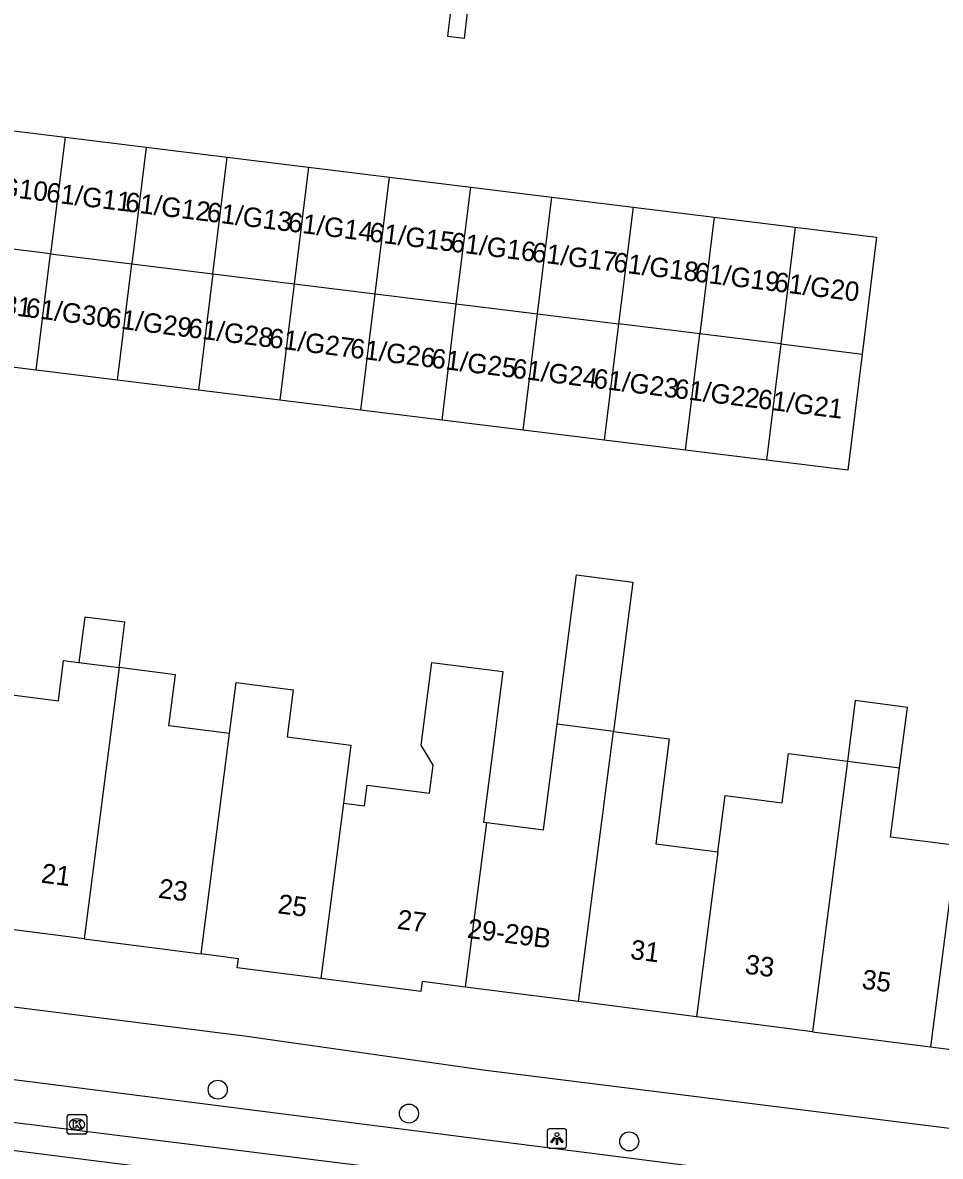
# Model space of a CAD drawing. Extents: x 161696 to 162377, y 380761 to 381673.
# Drawn here: x 161893.4 to 161940.5, y 381316.7 to 381375.1 of the extents above; entities that cross this region are included whole.
import ezdxf

# ---------------------------------------------------------------- set-up
doc = ezdxf.new("R2010")
doc.units = 0
for name, color, linetype in [('IMGEO_Boom', 7, 'Continuous'), ('IMGEO_Kolk', 7, 'Continuous'), ('IMGEO_Lichtpunt', 7, 'Continuous'), ('IMGEO_Pand', 7, 'Continuous'), ('IMGEO_Pand_nummerreeks', 7, 'Continuous'), ('IMGEO_Rijbaan_lokaal_gesloten', 7, 'Continuous'), ('IMGEO_Voetpad_open', 7, 'Continuous')]:
    doc.layers.add(name, color=color, linetype=linetype)

msp = doc.modelspace()

# ---------------------------------------------------------------- linework, layer by layer
at = {"layer": 'IMGEO_Boom'}
for centre in [(161903.383, 381320.171), (161913.22, 381318.941), (161924.549, 381317.51)]:
    msp.add_circle(centre, 0.489, dxfattribs=at)
at = {"layer": 'IMGEO_Kolk'}
for p, q in [((161895.646, 381317.96), (161895.646, 381318.812)), ((161895.721, 381318.886), (161896.573, 381318.886)), ((161896.647, 381318.812), (161896.647, 381317.96)), ((161896.134, 381318.666), (161896.159, 381318.666)), ((161896.573, 381317.886), (161895.721, 381317.886)), ((161896.157, 381318.106), (161896.132, 381318.106))]:
    msp.add_line(p, q, dxfattribs=at)
for points in [[(161895.646, 381317.96), (161895.646, 381318.812)], [(161895.721, 381318.886), (161896.573, 381318.886)], [(161896.647, 381318.812), (161896.647, 381317.96)], [(161895.967, 381318.586), (161896.09, 381318.586), (161896.09, 381318.435), (161896.22, 381318.586), (161896.384, 381318.586), (161896.238, 381318.435), (161896.391, 381318.186), (161896.239, 381318.186), (161896.154, 381318.35), (161896.09, 381318.283), (161896.09, 381318.186), (161895.967, 381318.186), (161895.967, 381318.586)], [(161896.573, 381317.886), (161895.721, 381317.886)]]:
    msp.add_lwpolyline(points, dxfattribs=at)
for centre, start, end in [((161895.723, 381318.81), 91.55205, 178.44795), ((161895.723, 381318.81), 91.55205, 178.44795), ((161896.571, 381318.81), 1.55205, 88.44795), ((161896.571, 381318.81), 1.55205, 88.44795), ((161895.723, 381317.962), 181.55205, 268.44795), ((161895.723, 381317.962), 181.55205, 268.44795), ((161896.571, 381317.962), 271.55205, 358.44795), ((161896.571, 381317.962), 271.55205, 358.44795)]:
    msp.add_arc(centre, 0.0765, start, end, dxfattribs=at)
for centre, major_axis, ratio, start_param, end_param in [((161896.133, 381318.386), (-0.387, 0.002), 0.722429, 4.712389, 7.853982), ((161896.158, 381318.386), (-0.39, 0.002), 0.717154, 1.570796, 4.712389)]:
    msp.add_ellipse(centre, major_axis=major_axis, ratio=ratio, start_param=start_param, end_param=end_param, dxfattribs=at)
at = {"layer": 'IMGEO_Lichtpunt'}
for p, q in [((161921.234, 381318.158), (161920.426, 381318.158)), ((161921.234, 381318.158), (161920.426, 381318.158)), ((161920.332, 381318.063), (161920.332, 381317.256)), ((161920.332, 381318.063), (161920.332, 381317.256)), ((161921.328, 381317.256), (161921.328, 381318.063)), ((161921.328, 381317.256), (161921.328, 381318.063)), ((161920.426, 381317.162), (161921.234, 381317.162)), ((161920.426, 381317.162), (161921.234, 381317.162))]:
    msp.add_line(p, q, dxfattribs=at)
for points in [[(161920.706, 381317.727), (161920.745, 381317.699), (161920.557, 381317.437), (161920.519, 381317.464), (161920.706, 381317.727)], [(161920.808, 381317.679), (161920.855, 381317.679), (161920.855, 381317.357), (161920.808, 381317.357), (161920.808, 381317.679)], [(161920.918, 381317.699), (161920.956, 381317.726), (161921.143, 381317.464), (161921.104, 381317.436), (161920.918, 381317.699)]]:
    msp.add_lwpolyline(points, dxfattribs=at)
msp.add_circle((161920.831, 381317.861), 0.0994, dxfattribs=at)
for centre, start, end in [((161920.426, 381318.063), 90, 180), ((161920.426, 381318.063), 90, 180), ((161921.234, 381318.063), 0, 90), ((161921.234, 381318.063), 0, 90), ((161920.426, 381317.256), 180, 270), ((161920.426, 381317.256), 180, 270), ((161921.234, 381317.256), 270, 0), ((161921.234, 381317.256), 270, 360)]:
    msp.add_arc(centre, 0.0946, start, end, dxfattribs=at)
at = {"layer": 'IMGEO_Pand'}
for points in [[(161915.217, 381374.347), (161915.253, 381374.661), (161915.3, 381375.07), (161915.573, 381377.467), (161915.598, 381377.683), (161916.454, 381377.582), (161916.429, 381377.366), (161916.358, 381376.764), (161916.097, 381374.561), (161916.06, 381374.247), (161915.217, 381374.347)], [(161891.357, 381369.683), (161895.53, 381369.17)], [(161895.53, 381369.17), (161894.791, 381363.166)], [(161895.53, 381369.17), (161899.704, 381368.656)], [(161899.704, 381368.656), (161898.964, 381362.652)], [(161899.704, 381368.656), (161903.877, 381368.142)], [(161903.137, 381362.137), (161903.877, 381368.142)], [(161903.877, 381368.142), (161908.05, 381367.628)], [(161908.05, 381367.628), (161907.31, 381361.622)], [(161908.05, 381367.628), (161912.223, 381367.114)], [(161911.483, 381361.107), (161912.223, 381367.114)], [(161912.223, 381367.114), (161916.396, 381366.6)], [(161915.656, 381360.592), (161916.396, 381366.6)], [(161916.396, 381366.6), (161920.569, 381366.086)], [(161919.829, 381360.078), (161920.569, 381366.086)], [(161920.569, 381366.086), (161924.743, 381365.572)], [(161924.743, 381365.572), (161924.002, 381359.563)], [(161924.743, 381365.572), (161928.916, 381365.058)], [(161928.916, 381365.058), (161928.176, 381359.048)], [(161928.916, 381365.058), (161933.089, 381364.544)], [(161933.089, 381364.544), (161932.349, 381358.533)], [(161933.089, 381364.544), (161937.262, 381364.03), (161936.522, 381358.018)], [(161894.791, 381363.166), (161890.618, 381363.681)], [(161894.054, 381357.181), (161894.791, 381363.166)], [(161894.791, 381363.166), (161898.964, 381362.652)], [(161898.227, 381356.667), (161898.964, 381362.652)], [(161898.964, 381362.652), (161903.137, 381362.137)], [(161903.137, 381362.137), (161902.4, 381356.153)], [(161903.137, 381362.137), (161907.31, 381361.622)], [(161907.31, 381361.622), (161906.573, 381355.639)], [(161907.31, 381361.622), (161911.483, 381361.107)], [(161910.747, 381355.125), (161911.483, 381361.107)], [(161911.483, 381361.107), (161915.656, 381360.592)], [(161914.92, 381354.611), (161915.656, 381360.592)], [(161915.656, 381360.592), (161919.829, 381360.078)], [(161919.093, 381354.098), (161919.829, 381360.078)], [(161919.829, 381360.078), (161924.002, 381359.563)], [(161924.002, 381359.563), (161923.266, 381353.584)], [(161928.176, 381359.048), (161924.002, 381359.563)], [(161927.439, 381353.07), (161928.176, 381359.048)], [(161932.349, 381358.533), (161928.176, 381359.048)], [(161932.349, 381358.533), (161931.612, 381352.556)], [(161932.349, 381358.533), (161936.522, 381358.018)], [(161936.522, 381358.018), (161935.786, 381352.042), (161931.612, 381352.556)], [(161894.054, 381357.181), (161889.881, 381357.695)], [(161898.227, 381356.667), (161894.054, 381357.181)], [(161902.4, 381356.153), (161898.227, 381356.667)], [(161906.573, 381355.639), (161902.4, 381356.153)], [(161910.747, 381355.125), (161906.573, 381355.639)], [(161914.92, 381354.611), (161910.747, 381355.125)], [(161919.093, 381354.098), (161914.92, 381354.611)], [(161923.266, 381353.584), (161919.093, 381354.098)], [(161927.439, 381353.07), (161923.266, 381353.584)], [(161931.612, 381352.556), (161927.439, 381353.07)], [(161920.843, 381338.97), (161921.532, 381344.314), (161921.834, 381346.661), (161924.73, 381346.288), (161923.875, 381339.654), (161923.739, 381338.597)], [(161898.309, 381341.882), (161898.61, 381344.22), (161896.547, 381344.487), (161896.245, 381342.148)], [(161891.941, 381339.132), (161892.127, 381340.577), (161895.191, 381340.182), (161895.457, 381342.25), (161896.245, 381342.148)], [(161896.245, 381342.148), (161898.309, 381341.882)], [(161909.848, 381334.907), (161910.935, 381334.767), (161911.073, 381335.837), (161914.282, 381335.424), (161914.468, 381336.864), (161913.846, 381337.902), (161914.394, 381342.152), (161918.053, 381341.681), (161917.759, 381339.402), (161917.636, 381338.447), (161917.055, 381333.937), (161917.226, 381333.915)], [(161898.309, 381341.882), (161896.511, 381327.93)], [(161903.99, 381338.488), (161900.876, 381338.889), (161901.214, 381341.508), (161898.309, 381341.882)], [(161903.99, 381338.488), (161904.328, 381341.112), (161907.259, 381340.735), (161906.947, 381338.315), (161910.233, 381337.891), (161909.848, 381334.907)], [(161938.453, 381336.733), (161938.853, 381339.84), (161936.175, 381340.185), (161935.775, 381337.078)], [(161917.226, 381333.915), (161920.143, 381333.539), (161920.843, 381338.97)], [(161923.739, 381338.597), (161920.843, 381338.97)], [(161921.948, 381324.702), (161923.739, 381338.597)], [(161923.739, 381338.597), (161926.61, 381338.227), (161925.912, 381332.812), (161929.106, 381332.4)], [(161902.529, 381327.155), (161903.629, 381335.69), (161903.99, 381338.488)], [(161929.106, 381332.4), (161929.481, 381335.309), (161932.417, 381334.931), (161932.744, 381337.469), (161935.775, 381337.078)], [(161935.775, 381337.078), (161933.981, 381323.151)], [(161935.775, 381337.078), (161938.453, 381336.733)], [(161941.14, 381330.858), (161941.381, 381332.727), (161937.994, 381333.163), (161938.453, 381336.733)], [(161909.848, 381334.907), (161908.686, 381325.888)], [(161916.136, 381325.45), (161917.226, 381333.915)], [(161929.106, 381332.4), (161928.013, 381323.92)], [(161941.14, 381330.858), (161941.07, 381330.318), (161940.047, 381322.37)], [(161896.511, 381327.93), (161890.596, 381328.692)], [(161896.511, 381327.93), (161902.529, 381327.155)], [(161908.686, 381325.888), (161904.387, 381326.442), (161904.447, 381326.908), (161902.529, 381327.155)], [(161916.136, 381325.45), (161913.896, 381325.739), (161913.83, 381325.225), (161908.686, 381325.888)], [(161921.948, 381324.702), (161916.136, 381325.45)], [(161928.013, 381323.92), (161921.948, 381324.702)], [(161933.981, 381323.151), (161928.013, 381323.92)], [(161933.981, 381323.151), (161940.047, 381322.37)], [(161940.047, 381322.37), (161946.215, 381321.575)]]:
    msp.add_lwpolyline(points, dxfattribs=at)
at = {"layer": 'IMGEO_Rijbaan_lokaal_gesloten'}
for points in [[(162011.888, 381305.414), (161977.562, 381309.831), (161938.099, 381314.908), (161875.004, 381322.955)], [(161874.726, 381320.753), (161937.716, 381312.93), (161976.665, 381307.938), (162014.292, 381303.079)], [(162014.081, 381301.54), (161976.129, 381306.423), (161924.33, 381313.049), (161874.551, 381319.364)]]:
    msp.add_lwpolyline(points, dxfattribs=at)
at = {"layer": 'IMGEO_Voetpad_open'}
msp.add_lwpolyline([(161796.224, 381336.573), (161797.3, 381336.438), (161904.754, 381322.94), (161917.03, 381321.199), (161941.301, 381318.149), (161957.474, 381315.915), (161987.264, 381312.217)], dxfattribs=at)

# ---------------------------------------------------------------- texts
at = {"layer": 'IMGEO_Pand_nummerreeks'}
for s, rotation, p in [('61/G10', 352.9716, (161890.232, 381366.393)), ('61/G11', 352.9716, (161894.521, 381365.864)), ('61/G12', 352.9716, (161898.588, 381365.363)), ('61/G13', 352.9716, (161902.776, 381364.846)), ('61/G14', 352.9716, (161906.958, 381364.331)), ('61/G15', 352.9716, (161911.141, 381363.815)), ('61/G16', 352.9716, (161915.323, 381363.299)), ('61/G17', 352.9716, (161919.505, 381362.784)), ('61/G18', 352.9716, (161923.691, 381362.268)), ('61/G19', 352.9716, (161927.867, 381361.753)), ('61/G20', 352.9716, (161931.965, 381361.248)), ('61/G31', 352.88379, (161889.405, 381360.435)), ('61/G30', 352.88379, (161893.47, 381359.927)), ('61/G29', 352.88379, (161897.636, 381359.407)), ('61/G28', 352.88379, (161901.814, 381358.886)), ('61/G27', 352.88379, (161905.983, 381358.365)), ('61/G26', 352.88379, (161910.155, 381357.844)), ('61/G25', 352.88379, (161914.327, 381357.324)), ('61/G24', 352.88379, (161918.499, 381356.803)), ('61/G23', 352.88379, (161922.67, 381356.282)), ('61/G22', 352.88379, (161926.836, 381355.762)), ('61/G21', 352.88379, (161931.124, 381355.227)), ('21', 352.60884, (161894.268, 381330.829)), ('23', 352.60884, (161900.294, 381330.047)), ('25', 352.60884, (161906.433, 381329.25)), ('27', 352.60884, (161912.572, 381328.454)), ('29-29B', 352.65138, (161916.178, 381327.987)), ('31', 352.65832, (161924.567, 381326.905)), ('33', 352.66041, (161930.465, 381326.146)), ('35', 352.66041, (161936.474, 381325.372))]:
    msp.add_text(s, height=1, rotation=rotation, dxfattribs=at).set_placement(p)

doc.saveas('drawing.dxf')
